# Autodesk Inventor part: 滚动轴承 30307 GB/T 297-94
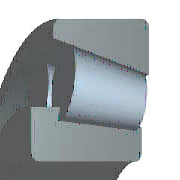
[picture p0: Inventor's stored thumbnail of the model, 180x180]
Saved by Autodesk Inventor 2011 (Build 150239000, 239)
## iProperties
Created: 2010-02
Part Number: 滚动轴承 30307 GB/T 297-94
Material: 低炭钢
Description: 滚动轴承 - 圆锥滚子轴承 - 外形尺寸
Document SubType Name: Modeling
Standard: GB/T 297-1994
Designer: Administrator
Standard Revision: 1994
Standards Organization: GB
Language: zh-CN
Size Designation: 30307
Categories: <MemberInstance><Categories><Category DisplayName="轴用零件" InternalName="7f7aeb1f-a693-4053-b835-cee3144e0d98" Mnemonic="SHFT"><Category DisplayName="轴承" Internal
Density: 1 g/cm^3
IsCustomPart: 1
Author: Administrator
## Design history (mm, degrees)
sketch "Sketch"
  geometry: L1 (5.146, 29.515)-(5.67, 33.782); L2 (4.75, 33.977)-(22.75, 30.151); L3 (17.994, 31.162)-(17.604, 27.985); L4 (5.146, 29.515)-(17.604, 27.985); L5 (5.146, 29.515)-(4.622, 25.248); L6 (4.622, 25.248)-(17.214, 24.808); L7 (17.214, 24.808)-(17.604, 27.985); L8 (0, 0)-(0, 17.5); L9 (0, 0)-(21, 0); L10 (17.289, 25.417)-(21, 25.417); L11 (21, 25.417)-(21, 17.5); L12 (21, 17.5)-(0, 17.5); L13 (0, 27.685)-(4.921, 27.685); L14 (0, 27.685)-(0, 17.5); L15 (22.75, 30.152)-(22.75, 40); L16 (22.75, 40)-(4.75, 40); L17 (4.75, 40)-(4.75, 33.978); L18 (11.375, 28.75)-(11.832, 32.472); L19 (4.75, 33.978)-(22.75, 30.152); L20 (4.75, 33.978)-(4.75, 33.977); L21 (22.75, 30.152)-(22.75, 30.151); L22 (11.832, 32.472)-(11.832, 32.473); L23 (17.214, 24.809)-(4.622, 25.249)
  constraints: 46 end point, 10 parallel, 9 point on line, 5 perpendicular, 2 collinear, 1 midpoint, 1 vertical, 3 other
  dimensions: "d0" = 12.6 distance of L5.end L6.end (= 0.7 x KAB); "d1" = 18 distance of L15.end L16.end (= KAB); "d2" = 35 diameter of L12 L9 (= WD); "d3" = 80 diameter of L16 L9 (= BD); "d4" = 21 distance of L11.end L8.end (= KB1); "d5" = 22.75 distance between parallel lines of L14 L15 (= KB); "d6" = 5 deg angle of L2 L4; "d7" = 3.75 distance of L18.end L18.start (= -0.0833333 x WD + 0.0833333 x BD); "d8" = 2.43717 distance from line of L13 L5.end (computed from BBB, KAB, BBA, BD, WD); "d9" = 0.60929 distance from line of L10 L6.end (computed from BBB, KAB, BBA, BD, WD); "d18" = 3.751 distance of L18.start L22.end (computed from d7); "d19" = 57.5 diameter of L18.start L9 (= 0.5 x WD + 0.5 x BD); "d20" = 7 deg angle of L4 L9 (computed from BBA); "d21" = 11.375 distance from line of L18.start L14 (= 0.5 x KB); "d69" = 0.001 distance between parallel lines of L6 L23
revolve "Body" stored, may be unused: angle "d50" = 90 deg
fillet "Fillet1" dims "d10" = 2 (= KR3S), "d11" = 2 (= KR1S)
revolve "Roller" stored, may be unused: angle "d53" = 90 deg
pattern_circular "Rollers" dims angle "d13" = 360 deg
body "Solid1"
other parameters: "WD" = 35 [user parameter; used in 7 equation terms], "BD" = 80 [user parameter; used in 7 equation terms], "KB" = 22.75 [user parameter; used in 2 equation terms], "KB1" = 21 [user parameter; used in 1 equation term], "KR1S" = 2 [user parameter; used in 2 equation terms], "KR3S" = 2 (= KR1S) [user parameter; used in 1 equation term], "BBA" = 12 deg [user parameter; used in 3 equation terms], "BBB" = 65.769 [user parameter; used in 2 equation terms], "KAB" = 18 [user parameter; used in 4 equation terms], "d14" = 0, "d15" = 0, "d16" = 0, "d17" = 0, "d70" = 0, "WR" = 17.5 (= 0.5 x WD) [user parameter], "BC0" = 8.25e+07 [user parameter], "BC" = 7.52e+07 [user parameter]
